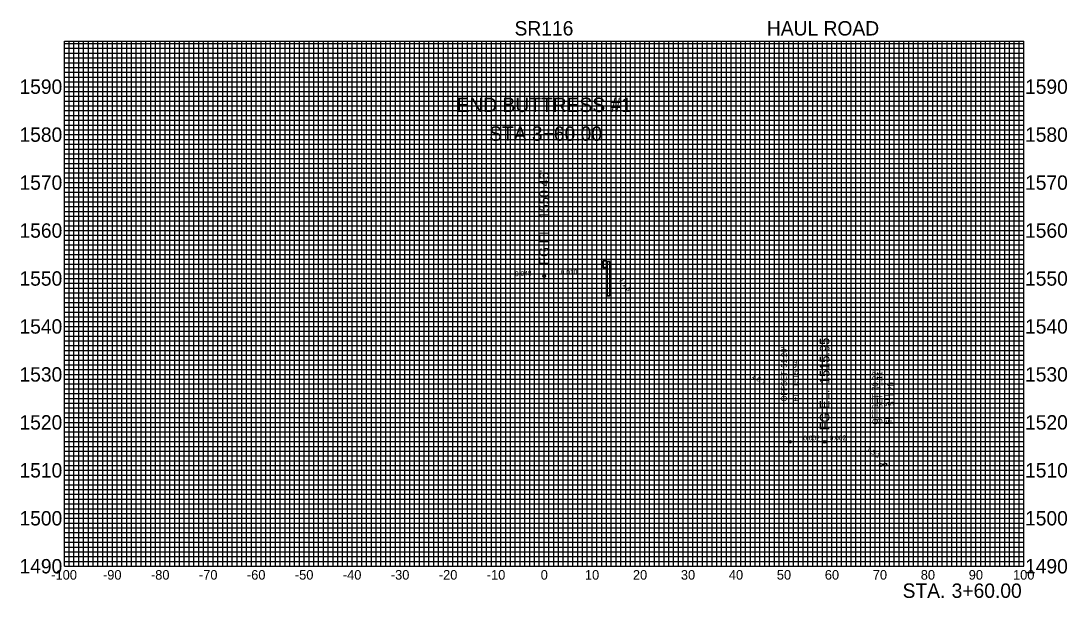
# Model space of a CAD drawing. Extents: x -109 to 109, y 1483 to 1604.
import ezdxf

# ---------------------------------------------------------------- set-up
doc = ezdxf.new("R2010")
doc.units = 0
for name, color, linetype in [('DES - SHEET - Light Grid', 7, 'Continuous'), ('DES - SHEET - Linework', 7, 'Continuous'), ('DES - XS - Proposed - Finished Grade Slopes Text', 7, 'Continuous'), ('DES - XS - Proposed - Guardrail', 7, 'Continuous'), ('DES - XS - Proposed - Text', 7, 'Continuous')]:
    doc.layers.add(name, color=color, linetype=linetype)

msp = doc.modelspace()

# ---------------------------------------------------------------- linework, layer by layer
at = {"layer": 'DES - SHEET - Light Grid'}
for p, q in [((-100, 1599), (100, 1599)), ((-99, 1490), (-99, 1599.47)), ((-98, 1490), (-98, 1599.47)), ((-97, 1490), (-97, 1599.47)), ((-96, 1490), (-96, 1599.47)), ((-95, 1490), (-95, 1599.47)), ((-94, 1490), (-94, 1599.47)), ((-93, 1490), (-93, 1599.47)), ((-92, 1490), (-92, 1599.47)), ((-91, 1490), (-91, 1599.47)), ((-89, 1490), (-89, 1599.47)), ((-88, 1490), (-88, 1599.47)), ((-87, 1490), (-87, 1599.47)), ((-86, 1490), (-86, 1599.47)), ((-85, 1490), (-85, 1599.47)), ((-84, 1490), (-84, 1599.47)), ((-83, 1490), (-83, 1599.47)), ((-82, 1490), (-82, 1599.47)), ((-81, 1490), (-81, 1599.47)), ((-79, 1490), (-79, 1599.47)), ((-78, 1490), (-78, 1599.47)), ((-77, 1490), (-77, 1599.47)), ((-76, 1490), (-76, 1599.47)), ((-75, 1490), (-75, 1599.47)), ((-74, 1490), (-74, 1599.47)), ((-73, 1490), (-73, 1599.47)), ((-72, 1490), (-72, 1599.47)), ((-71, 1490), (-71, 1599.47)), ((-69, 1490), (-69, 1599.47)), ((-68, 1490), (-68, 1599.47)), ((-67, 1490), (-67, 1599.47)), ((-66, 1490), (-66, 1599.47)), ((-65, 1490), (-65, 1599.47)), ((-64, 1490), (-64, 1599.47)), ((-63, 1490), (-63, 1599.47)), ((-62, 1490), (-62, 1599.47)), ((-61, 1490), (-61, 1599.47)), ((-59, 1490), (-59, 1599.47)), ((-58, 1490), (-58, 1599.47)), ((-57, 1490), (-57, 1599.47)), ((-56, 1490), (-56, 1599.47)), ((-55, 1490), (-55, 1599.47)), ((-54, 1490), (-54, 1599.47)), ((-53, 1490), (-53, 1599.47)), ((-52, 1490), (-52, 1599.47)), ((-51, 1490), (-51, 1599.47)), ((-49, 1490), (-49, 1599.47)), ((-48, 1490), (-48, 1599.47)), ((-47, 1490), (-47, 1599.47)), ((-46, 1490), (-46, 1599.47)), ((-45, 1490), (-45, 1599.47)), ((-44, 1490), (-44, 1599.47)), ((-43, 1490), (-43, 1599.47)), ((-42, 1490), (-42, 1599.47)), ((-41, 1490), (-41, 1599.47)), ((-39, 1490), (-39, 1599.47)), ((-38, 1490), (-38, 1599.47)), ((-37, 1490), (-37, 1599.47)), ((-36, 1490), (-36, 1599.47)), ((-35, 1490), (-35, 1599.47)), ((-34, 1490), (-34, 1599.47)), ((-33, 1490), (-33, 1599.47)), ((-32, 1490), (-32, 1599.47)), ((-31, 1490), (-31, 1599.47)), ((-29, 1490), (-29, 1599.47)), ((-28, 1490), (-28, 1599.47)), ((-27, 1490), (-27, 1599.47)), ((-26, 1490), (-26, 1599.47)), ((-25, 1490), (-25, 1599.47)), ((-24, 1490), (-24, 1599.47)), ((-23, 1490), (-23, 1599.47)), ((-22, 1490), (-22, 1599.47)), ((-21, 1490), (-21, 1599.47)), ((-19, 1490), (-19, 1599.47)), ((-18, 1490), (-18, 1599.47)), ((-17, 1490), (-17, 1599.47)), ((-16, 1490), (-16, 1599.47)), ((-15, 1490), (-15, 1599.47)), ((-14, 1490), (-14, 1599.47)), ((-13, 1490), (-13, 1599.47)), ((-12, 1490), (-12, 1599.47)), ((-11, 1490), (-11, 1599.47)), ((-9, 1490), (-9, 1599.47)), ((-8, 1490), (-8, 1599.47)), ((-7, 1490), (-7, 1599.47)), ((-6, 1490), (-6, 1599.47)), ((-5, 1490), (-5, 1599.47)), ((-4, 1490), (-4, 1599.47)), ((-3, 1490), (-3, 1599.47)), ((-2, 1490), (-2, 1599.47)), ((-1, 1490), (-1, 1599.47)), ((1, 1490), (1, 1599.47)), ((2, 1490), (2, 1599.47)), ((3, 1490), (3, 1599.47)), ((4, 1490), (4, 1599.47)), ((5, 1490), (5, 1599.47)), ((6, 1490), (6, 1599.47)), ((7, 1490), (7, 1599.47)), ((8, 1490), (8, 1599.47)), ((9, 1490), (9, 1599.47)), ((11, 1490), (11, 1599.47)), ((12, 1490), (12, 1599.47)), ((13, 1490), (13, 1599.47)), ((14, 1490), (14, 1599.47)), ((15, 1490), (15, 1599.47)), ((16, 1490), (16, 1599.47)), ((17, 1490), (17, 1599.47)), ((18, 1490), (18, 1599.47)), ((19, 1490), (19, 1599.47)), ((21, 1490), (21, 1599.47)), ((22, 1490), (22, 1599.47)), ((23, 1490), (23, 1599.47)), ((24, 1490), (24, 1599.47)), ((25, 1490), (25, 1599.47)), ((26, 1490), (26, 1599.47)), ((27, 1490), (27, 1599.47)), ((28, 1490), (28, 1599.47)), ((29, 1490), (29, 1599.47)), ((31, 1490), (31, 1599.47)), ((32, 1490), (32, 1599.47)), ((33, 1490), (33, 1599.47)), ((34, 1490), (34, 1599.47)), ((35, 1490), (35, 1599.47)), ((36, 1490), (36, 1599.47)), ((37, 1490), (37, 1599.47)), ((38, 1490), (38, 1599.47)), ((39, 1490), (39, 1599.47)), ((41, 1490), (41, 1599.47)), ((42, 1490), (42, 1599.47)), ((43, 1490), (43, 1599.47)), ((44, 1490), (44, 1599.47)), ((45, 1490), (45, 1599.47)), ((46, 1490), (46, 1599.47)), ((47, 1490), (47, 1599.47)), ((48, 1490), (48, 1599.47)), ((49, 1490), (49, 1599.47)), ((51, 1490), (51, 1599.47)), ((52, 1490), (52, 1599.47)), ((53, 1490), (53, 1599.47)), ((54, 1490), (54, 1599.47)), ((55, 1490), (55, 1599.47)), ((56, 1490), (56, 1599.47)), ((57, 1490), (57, 1599.47)), ((58, 1490), (58, 1599.47)), ((59, 1490), (59, 1599.47)), ((61, 1490), (61, 1599.47)), ((62, 1490), (62, 1599.47)), ((63, 1490), (63, 1599.47)), ((64, 1490), (64, 1599.47)), ((65, 1490), (65, 1599.47)), ((66, 1490), (66, 1599.47)), ((67, 1490), (67, 1599.47)), ((68, 1490), (68, 1599.47)), ((69, 1490), (69, 1599.47)), ((71, 1490), (71, 1599.47)), ((72, 1490), (72, 1599.47)), ((73, 1490), (73, 1599.47)), ((74, 1490), (74, 1599.47)), ((75, 1490), (75, 1599.47)), ((76, 1490), (76, 1599.47)), ((77, 1490), (77, 1599.47)), ((78, 1490), (78, 1599.47)), ((79, 1490), (79, 1599.47)), ((81, 1490), (81, 1599.47)), ((82, 1490), (82, 1599.47)), ((83, 1490), (83, 1599.47)), ((84, 1490), (84, 1599.47)), ((85, 1490), (85, 1599.47)), ((86, 1490), (86, 1599.47)), ((87, 1490), (87, 1599.47)), ((88, 1490), (88, 1599.47)), ((89, 1490), (89, 1599.47)), ((91, 1490), (91, 1599.47)), ((92, 1490), (92, 1599.47)), ((93, 1490), (93, 1599.47)), ((94, 1490), (94, 1599.47)), ((95, 1490), (95, 1599.47)), ((96, 1490), (96, 1599.47)), ((97, 1490), (97, 1599.47)), ((98, 1490), (98, 1599.47)), ((99, 1490), (99, 1599.47)), ((-100, 1598), (100, 1598)), ((-100, 1597), (100, 1597)), ((-100, 1596), (100, 1596)), ((-100, 1595), (100, 1595)), ((-100, 1594), (100, 1594)), ((-100, 1593), (100, 1593)), ((-100, 1592), (100, 1592)), ((-100, 1591), (100, 1591)), ((-100, 1589), (100, 1589)), ((-100, 1588), (100, 1588)), ((-100, 1587), (100, 1587)), ((-100, 1586), (100, 1586)), ((-100, 1585), (100, 1585)), ((-100, 1584), (100, 1584)), ((-100, 1583), (100, 1583)), ((-100, 1582), (100, 1582)), ((-100, 1581), (100, 1581)), ((-100, 1579), (100, 1579)), ((-100, 1578), (100, 1578)), ((-100, 1577), (100, 1577)), ((-100, 1576), (100, 1576)), ((-100, 1575), (100, 1575)), ((-100, 1574), (100, 1574)), ((-100, 1573), (100, 1573)), ((-100, 1572), (100, 1572)), ((-100, 1571), (100, 1571)), ((-100, 1569), (100, 1569)), ((-100, 1568), (100, 1568)), ((-100, 1567), (100, 1567)), ((-100, 1566), (100, 1566)), ((-100, 1565), (100, 1565)), ((-100, 1564), (100, 1564)), ((-100, 1563), (100, 1563)), ((-100, 1562), (100, 1562)), ((-100, 1561), (100, 1561)), ((-100, 1559), (100, 1559)), ((-100, 1558), (100, 1558)), ((-100, 1557), (100, 1557)), ((-100, 1556), (100, 1556)), ((-100, 1555), (100, 1555)), ((-100, 1554), (100, 1554)), ((-100, 1553), (100, 1553)), ((-100, 1552), (100, 1552)), ((-100, 1551), (100, 1551)), ((-100, 1549), (100, 1549)), ((-100, 1548), (100, 1548)), ((-100, 1547), (100, 1547)), ((-100, 1546), (100, 1546)), ((-100, 1545), (100, 1545)), ((-100, 1544), (100, 1544)), ((-100, 1543), (100, 1543)), ((-100, 1542), (100, 1542)), ((-100, 1541), (100, 1541)), ((-100, 1539), (100, 1539)), ((-100, 1538), (100, 1538)), ((-100, 1537), (100, 1537)), ((-100, 1536), (100, 1536)), ((-100, 1535), (100, 1535)), ((-100, 1534), (100, 1534)), ((-100, 1533), (100, 1533)), ((-100, 1532), (100, 1532)), ((-100, 1531), (100, 1531)), ((-100, 1529), (100, 1529)), ((-100, 1528), (100, 1528)), ((-100, 1527), (100, 1527)), ((-100, 1526), (100, 1526)), ((-100, 1525), (100, 1525)), ((-100, 1524), (100, 1524)), ((-100, 1523), (100, 1523)), ((-100, 1522), (100, 1522)), ((-100, 1521), (100, 1521)), ((-100, 1519), (100, 1519)), ((-100, 1518), (100, 1518)), ((-100, 1517), (100, 1517)), ((-100, 1516), (100, 1516)), ((-100, 1515), (100, 1515)), ((-100, 1514), (100, 1514)), ((-100, 1513), (100, 1513)), ((-100, 1512), (100, 1512)), ((-100, 1511), (100, 1511)), ((-100, 1509), (100, 1509)), ((-100, 1508), (100, 1508)), ((-100, 1507), (100, 1507)), ((-100, 1506), (100, 1506)), ((-100, 1505), (100, 1505)), ((-100, 1504), (100, 1504)), ((-100, 1503), (100, 1503)), ((-100, 1502), (100, 1502)), ((-100, 1501), (100, 1501)), ((-100, 1499), (100, 1499)), ((-100, 1498), (100, 1498)), ((-100, 1497), (100, 1497)), ((-100, 1496), (100, 1496)), ((-100, 1495), (100, 1495)), ((-100, 1494), (100, 1494)), ((-100, 1493), (100, 1493)), ((-100, 1492), (100, 1492)), ((-100, 1491), (100, 1491))]:
    msp.add_line(p, q, dxfattribs=at)
at = {"layer": 'DES - SHEET - Linework'}
for p, q in [((-100, 1599.47), (100, 1599.47)), ((-100, 1490), (-100, 1599.47)), ((-90, 1490), (-90, 1599.47)), ((-80, 1490), (-80, 1599.47)), ((-70, 1490), (-70, 1599.47)), ((-60, 1490), (-60, 1599.47)), ((-50, 1490), (-50, 1599.47)), ((-40, 1490), (-40, 1599.47)), ((-30, 1490), (-30, 1599.47)), ((-20, 1490), (-20, 1599.47)), ((-10, 1490), (-10, 1599.47)), ((0, 1490), (0, 1599.47)), ((10, 1490), (10, 1599.47)), ((20, 1490), (20, 1599.47)), ((30, 1490), (30, 1599.47)), ((40, 1490), (40, 1599.47)), ((50, 1490), (50, 1599.47)), ((60, 1490), (60, 1599.47)), ((70, 1490), (70, 1599.47)), ((80, 1490), (80, 1599.47)), ((90, 1490), (90, 1599.47)), ((100, 1490), (100, 1599.47)), ((-100, 1590), (100, 1590)), ((-100, 1580), (100, 1580)), ((-100, 1570), (100, 1570)), ((-100, 1560), (100, 1560)), ((-100, 1550), (100, 1550)), ((-100, 1540), (100, 1540)), ((-100, 1530), (100, 1530)), ((-100, 1520), (100, 1520)), ((-100, 1510), (100, 1510)), ((-100, 1500), (100, 1500)), ((-100, 1490), (100, 1490))]:
    msp.add_line(p, q, dxfattribs=at)
at = {"layer": 'DES - XS - Proposed - Finished Grade Slopes Text'}
for centre in [(51.2, 1515.94), (70.22, 1511.12), (71.11, 1511.2)]:
    msp.add_circle(centre, 0.3, dxfattribs=at)
at = {"layer": 'DES - XS - Proposed - Guardrail'}
for p, q in [((12.17, 1553.52), (12.04, 1553.42)), ((12.04, 1553.27), (12.29, 1553.09)), ((12.29, 1552.83), (12.04, 1552.65)), ((12.33, 1553.57), (12.29, 1553.57)), ((12.33, 1553.02), (12.33, 1552.9)), ((12.34, 1553.67), (12.34, 1553.67)), ((12.34, 1553.67), (13.09, 1553.67)), ((13.09, 1553.67), (12.34, 1553.67)), ((12.34, 1553.67), (12.34, 1552.27)), ((12.34, 1553.67), (12.34, 1552.27)), ((13.09, 1553.67), (13.09, 1553.67)), ((13.09, 1553.67), (13.09, 1552.27)), ((13.09, 1553.67), (13.09, 1552.27)), ((13.09, 1553.56), (13.09, 1553.56)), ((13.09, 1553.56), (13.11, 1553.56)), ((13.11, 1553.56), (13.09, 1553.56)), ((13.09, 1553.56), (13.09, 1546.36)), ((13.09, 1553.56), (13.09, 1546.36)), ((13.11, 1553.56), (13.11, 1553.56)), ((13.11, 1553.56), (13.66, 1553.56)), ((13.66, 1553.56), (13.11, 1553.56)), ((13.11, 1553.56), (13.11, 1553.56)), ((13.11, 1553.56), (13.11, 1546.36)), ((13.11, 1553.56), (13.11, 1546.36)), ((13.11, 1553.56), (13.11, 1546.36)), ((13.11, 1553.56), (13.11, 1546.36)), ((13.66, 1553.56), (13.66, 1553.56)), ((13.66, 1553.56), (13.68, 1553.56)), ((13.68, 1553.56), (13.66, 1553.56)), ((13.66, 1553.56), (13.66, 1553.56)), ((13.66, 1553.56), (13.66, 1546.36)), ((13.66, 1553.56), (13.66, 1546.36)), ((13.66, 1553.56), (13.66, 1546.36)), ((13.66, 1553.56), (13.66, 1546.36)), ((13.68, 1553.56), (13.68, 1553.56)), ((13.68, 1553.56), (13.68, 1546.36)), ((13.68, 1553.56), (13.68, 1546.36)), ((12.04, 1552.5), (12.17, 1552.4)), ((12.29, 1552.35), (12.33, 1552.35)), ((12.34, 1552.27), (12.34, 1552.27)), ((12.34, 1552.27), (13.09, 1552.27)), ((13.09, 1552.27), (12.34, 1552.27)), ((13.09, 1552.27), (13.09, 1552.27)), ((13.09, 1546.36), (13.09, 1546.36)), ((13.09, 1546.36), (13.11, 1546.36)), ((13.11, 1546.36), (13.09, 1546.36)), ((13.11, 1546.36), (13.11, 1546.36)), ((13.11, 1546.36), (13.66, 1546.36)), ((13.66, 1546.36), (13.11, 1546.36)), ((13.11, 1546.36), (13.11, 1546.36)), ((13.66, 1546.36), (13.66, 1546.36)), ((13.66, 1546.36), (13.68, 1546.36)), ((13.68, 1546.36), (13.66, 1546.36)), ((13.66, 1546.36), (13.66, 1546.36)), ((13.68, 1546.36), (13.68, 1546.36))]:
    msp.add_line(p, q, dxfattribs=at)
for centre, radius, start, end in [((12.09, 1553.35), 0.0938, 125, 235), ((12.09, 1552.57), 0.0938, 125, 235), ((12.34, 1553.27), 0.3, 100, 125), ((12.24, 1553.02), 0.0938, 0, 55), ((12.24, 1552.9), 0.0937, 305, 0), ((12.34, 1552.65), 0.3, 235, 260)]:
    msp.add_arc(centre, radius, start, end, dxfattribs=at)
at = {"layer": 'DES - XS - Proposed - Text'}
for centre in [(0, 1550.46), (58.47, 1515.95)]:
    msp.add_circle(centre, 0.3, dxfattribs=at)

# ---------------------------------------------------------------- texts
at = {"layer": 'DES - XS - Proposed - Finished Grade Slopes Text'}
for s, height, rotation, p in [('-0.048', 1, 2.775, (-6.5, 1550.44)), ('0.010', 1, 0.5922, (3.47, 1550.8)), ('1:1.3', 1, 308.6598, (15.57, 1549.58)), ("51.20'", 1.2, 90, (50.6, 1531.39)), ('1515.94', 1.2, 90, (53, 1527.32)), ("70.22'", 1.2, 90, (69.62, 1526.57)), ("71.11'", 1.2, 90, (70.51, 1526.65)), ('1.5:1', 1, 326.3086, (43.19, 1529.44)), ('OFFSET ', 1.2, 90, (50.6, 1524.34)), ('EL. ', 1.2, 90, (53, 1524.34)), ('1511.12', 1.2, 90, (72.02, 1522.5)), ('1511.20', 1.2, 90, (72.91, 1522.58)), ('OFFSET ', 1.2, 90, (69.62, 1519.52)), ('OFFSET ', 1.2, 90, (70.51, 1519.6)), ('EL. ', 1.2, 90, (72.02, 1519.52)), ('EL. ', 1.2, 90, (72.91, 1519.6)), ('0.002', 1, 0.1143, (54.02, 1516.24)), ('0.002', 1, 0.1073, (59.51, 1516.26)), ('1.5:1', 1, 326.3267, (67.1, 1514.17))]:
    msp.add_text(s, height=height, rotation=rotation, dxfattribs=at).set_placement(p)
at = {"layer": 'DES - XS - Proposed - Text'}
for s, height, p in [('SR116', 3, (-6.16, 1600.67)), ('HAUL ROAD', 3, (46.43, 1600.67)), ('1590', 3, (-109.36, 1588.5)), ('1590', 3, (100.24, 1588.5)), ('END BUTTRESS #1', 3, (-18.26, 1584.71)), ('1580', 3, (-109.36, 1578.5)), ('STA 3+60.00', 3, (-11.46, 1578.71)), ('1580', 3, (100.24, 1578.5)), ('1570', 3, (-109.36, 1568.5)), ('1570', 3, (100.24, 1568.5)), ('1560', 3, (-109.36, 1558.5)), ('1560', 3, (100.24, 1558.5)), ('1550', 3, (-109.36, 1548.5)), ('1550', 3, (100.24, 1548.5)), ('1540', 3, (-109.36, 1538.5)), ('1540', 3, (100.24, 1538.5)), ('1530', 3, (-109.36, 1528.5)), ('1530', 3, (100.24, 1528.5)), ('1520', 3, (-109.36, 1518.5)), ('1520', 3, (100.24, 1518.5)), ('1510', 3, (-109.36, 1508.5)), ('1510', 3, (100.24, 1508.5)), ('1500', 3, (-109.36, 1498.5)), ('1500', 3, (100.24, 1498.5)), ('1490', 3, (-109.36, 1488.5)), ('1490', 3, (100.24, 1488.5)), ('-100', 2, (-102.73, 1487.2)), ('-90', 2, (-91.95, 1487.2)), ('-80', 2, (-81.95, 1487.2)), ('-70', 2, (-71.95, 1487.2)), ('-60', 2, (-61.95, 1487.2)), ('-50', 2, (-51.95, 1487.2)), ('-40', 2, (-41.95, 1487.2)), ('-30', 2, (-31.95, 1487.2)), ('-20', 2, (-21.95, 1487.2)), ('-10', 2, (-11.95, 1487.2)), ('0', 2, (-0.71, 1487.2)), ('10', 2, (8.51, 1487.2)), ('20', 2, (18.51, 1487.2)), ('30', 2, (28.51, 1487.2)), ('40', 2, (38.51, 1487.2)), ('50', 2, (48.51, 1487.2)), ('60', 2, (58.51, 1487.2)), ('70', 2, (68.51, 1487.2)), ('80', 2, (78.51, 1487.2)), ('90', 2, (88.51, 1487.2)), ('100', 2, (97.74, 1487.2)), (' STA. ', 3, (73.61, 1483.4)), ('3+60.00', 3, (84.94, 1483.4))]:
    msp.add_text(s, height=height, dxfattribs=at).set_placement(p)
for s, p in [("1550.46'", (1, 1562.49)), ('FG EL. ', (1, 1552.86)), ("1515.95'", (59.47, 1527.98)), ('FG EL. ', (59.47, 1518.35))]:
    msp.add_text(s, height=2, rotation=90, dxfattribs=at).set_placement(p)

doc.saveas('drawing.dxf')
